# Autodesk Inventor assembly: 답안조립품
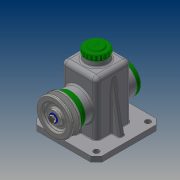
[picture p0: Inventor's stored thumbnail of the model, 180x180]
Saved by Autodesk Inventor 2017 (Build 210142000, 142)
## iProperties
Part Number: 답안조립품
Material: 일반
Document SubType Name: Assembly
Designer: 20
Author: 20
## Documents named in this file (14)
- C:\Users\20\Desktop\470818V1012\답안조립품.iam
- C:\Users\20\Desktop\470818V1012\본체.ipt
- C:\Users\20\Desktop\470818V1012\뒤커버.ipt
- C:\Users\20\Desktop\470818V1012\앞커버.ipt
- C:\Users\20\Desktop\470818V1012\베어링 15 x 35 x 11.ipt
- C:\Users\20\Desktop\470818V1012\오일실 15 25 7.ipt
- C:\Users\20\Desktop\470818V1012\축.ipt
- C:\Users\20\Desktop\470818V1012\멈춤링 15 x 1.ipt
- C:\Users\20\Desktop\470818V1012\볼트 M4 x 10.ipt
- C:\Users\20\Desktop\470818V1012\키 5 x 5 x 14.ipt
- C:\Users\20\Desktop\470818V1012\V-벨트풀리.ipt
- C:\Users\20\Desktop\470818V1012\볼트 M6 x 12.ipt
- C:\Users\20\Desktop\470818V1012\와셔.ipt
- C:\Users\20\Desktop\470818V1012\상부캡.ipt
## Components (1 placed, 1 different names)
1. V-벨트풀리:1
